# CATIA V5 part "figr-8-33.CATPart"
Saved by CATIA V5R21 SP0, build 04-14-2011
Part number: Part1
Bounding box of the stored display mesh (mm): x -75 to 75, y -75 to 75, z 0 to 20
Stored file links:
  D:\CATIA V5R21 E-RESOURCES\CATIA-V5R21\catia-v5r21-prt\c08-catia-v5r20-prt\c08-catia-v5r21-figr-8-33.CATPart
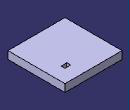
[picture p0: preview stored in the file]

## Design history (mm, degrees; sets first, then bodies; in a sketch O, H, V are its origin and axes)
Body1 (main body)
  Sketch1 on xy-plane, origin (0, 0, 0), H (1, 0, 0), V (0, 1, 0)
    line L1 (-75, 75) -> (75, 75)
    line L2 (75, 75) -> (75, -75)
    line L3 (75, -75) -> (-75, -75)
    line L4 (-75, -75) -> (-75, 75)
    axis line L5 (75, -75) -> (-75, 75)
    length L3 = 150
    length L2 = 150
    horizontal: L1 H, L3 H
    vertical: L2 V, L4 V
    midpoint: O L5
  Pad1: profile Sketch1, direction (0, 0, 1), length 20
  Sketch2 on face of Pad1, origin (0, 0, 20), H (1, 0, 0), V (0, 1, 0)
    line L1 (25, 40) -> (40, 40)
    line L2 (40, 40) -> (40, 30)
    line L3 (40, 30) -> (25, 30)
    line L4 (25, 30) -> (25, 40)
    reference projected line E1 (75, -75) -> (75, 75) from edge [face of Pad1 | face of Pad1]
    reference projected line E2 (75, 75) -> (-75, 75) from edge [face of Pad1 | face of Pad1]
    length L3 = 15
    length L4 = 10
    distance L2 E1 = 35
    distance L1 E2 = 35
    horizontal: L1 H, L3 H
    vertical: L2 V, L4 V
  Pocket1: profile Sketch2, direction (0, 0, -1), through (limit type 3)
